Omron CX-Programmer project 新工程 (CX-Programmer 9.40)

# PLC 新PLC1: CP1H XA

## Program 新程序1 (cyclic task 0)
Local symbols
CIO0 BOOL

### Section 段1

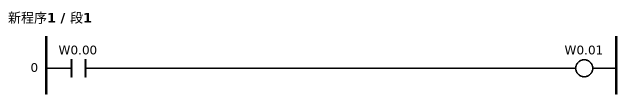
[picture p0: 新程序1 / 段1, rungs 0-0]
; rung 0
LD W0.00
OUT W0.01

### Section END
; rung 0
END(001)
